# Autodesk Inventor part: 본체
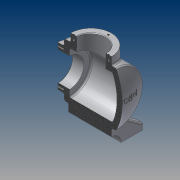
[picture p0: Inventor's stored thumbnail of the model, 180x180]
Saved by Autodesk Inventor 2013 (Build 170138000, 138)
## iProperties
Created: 2017-04
Part Number: 본체
Material: 알루미늄 6061
Document SubType Name: Modeling
Designer: Administrator
Density: 2.71 g/cm^3
Mass: 1670.76 g
Surface Area: 1066.85 cm^2
Volume: 616.515 cm^3
Author: Administrator
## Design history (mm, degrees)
sketch "스케치1"
  geometry: L1 (40, -60)-(-40, -60); L2 (-40, -60)-(-40, 60); L3 (-40, 60)-(40, 60); L4 (40, 60)-(40, -60); 3 further points
  constraints: 8 end point, 2 midpoint, 2 parallel, 1 horizontal, 1 horizontal alignment, 1 perpendicular, 1 vertical alignment
  dimensions: "d0" = 80 distance of L2.end L3.end; "d2" = 120 distance of L1.end L2.end
extrude "돌출1" new body sketch "스케치1" distance "d3" = 10; taper "d4" = 0 deg
sketch "스케치3"
  geometry: L1 (-60, 82)-(60, 82); L2 (-40, 0)-(-40, 10) reference; L3 (-40, 10)-(40, 10) reference; L4 (40, 10)-(40, 0) reference; L5 (40, 0)-(-40, 0) reference; L6 (-60, 82)-(-60, 120); L7 (-60, 120)-(-48, 120); L8 (-48, 120)-(-48, 132); L9 (-48, 132)-(48.336, 132); A1 r 113 centre (-53, 82) between (60, 82) and (48.336, 132); 2 further points
  constraints: 10 end point, 2 parallel, 2 perpendicular, 2 point on circle, 1 centre point, 1 horizontal, 1 midpoint, 1 point on line, 1 vertical alignment
  dimensions: "d5" = 82 distance between parallel lines of L5 L1; "d6" = 120 distance of L1.start L1.end; "d7" = 76 diameter of L7 L1; "d8" = 100 diameter of L9 L1; "d11" = 113 radius of A1; "d104" = 108 distance from line of L1.end L8
revolve "회전1" sketch "스케치3" stored, may be unused: angle "d12" = 90 deg
sketch "스케치4"
  geometry: L1 (-40, 0)-(-40, 10) reference; L2 (-40, 10)-(40, 10) reference; L3 (40, 10)-(40, 0) reference; L4 (40, 0)-(-40, 0) reference; L5 (-60, 44)-(-60, 120) reference; L6 (-60, 120)-(-48, 120) reference; L7 (-48, 120)-(-48, 132) reference; L8 (-48, 132)-(48.336, 132) reference; L9 (48.336, 32)-(-48, 32) reference; L10 (-48, 32)-(-48, 44) reference; L11 (-48, 44)-(-60, 44) reference; L12 (-60, 82)-(60, 82); L13 (41.916, 122)-(-38, 122); L14 (-38, 122)-(-38, 109); L15 (-38, 109)-(-60, 109); A1 r 113 centre (-53, 82) between (48.336, 32) and (48.336, 132) reference; A2 r 103 centre (-53, 82) between (50, 82) and (41.916, 122); 1 further point
  constraints: 8 end point, 3 point on circle, 2 point on line, 1 centre point, 1 midpoint, 1 other
  dimensions: "d14" = 10 radial gap between concentric circles of A1 A2; "d15" = 54 diameter of L15 L12; "d16" = 80 diameter of L13 L12
revolve "회전2" sketch "스케치4" stored, may be unused: angle "d17" = 90 deg
node "작업 평면1"
sketch "스케치5"
  geometry: L1 (48, 50)-(48, -50) reference; C1 r 38 at (-2, 0); 1 further point
  constraints: 1 centre point, 1 horizontal alignment
  dimensions: "d81" = 76 diameter of C1; "d82" = 50 distance from line of L1 C1.centre
extrude "돌출2" join sketch "스케치5" stored distance "d20" = 10; taper "d21" = 0 deg
sketch "스케치7" dims "d25" = 65
  geometry: C1 r 27 at (0, 0) reference; C2 r 38 at (0, 0) reference; 3 further points
  constraints: 2 vertical alignment, 1 coincident, 2 other
hole "구멍1" sketch "스케치7" at (0, 32.5) diameter "d26" = 3.242; stored, may be unused: countersink angle "d30" = 90 deg, drill point angle "d32" = 120 deg; dims "d27" = 8, "d28" = 4, "d29" = 2, "d31" = 10
sketch "스케치9"
  geometry: L1 (120, 0)-(120, 10) reference; L2 (0, 0)-(0, 10) reference; L3 (120, 10)-(120, 0) reference; L4 (120, 0)-(0, 0) reference; L5 (0, 0)-(0, 10) reference; L6 (0, 10)-(120, 10) reference; L7 (120, 10)-(81.584, 36.899); L8 (0, 10)-(38.416, 36.899); C1 r 27 at (60, 82) reference; A1 r 50 centre (60, 82) between (81.584, 36.899) and (38.416, 36.899) reference; 1 further point
  constraints: 4 end point, 2 point on circle
  dimensions: "d48" = 55 deg angle of L1 L7; "d49" = 55 deg angle of L2 L8
extrude "돌출4" join sketch "스케치9" distance "d50" = 80; taper "d51" = 0 deg
sketch "스케치10"
  geometry: L1 (120, 0)-(0, 0) reference; C1 r 18 at (60, 0); 2 further points
  constraints: 1 centre point, 1 coincident, 1 midpoint
  dimensions: "d52" = 36 diameter of C1
extrude "돌출5" cut sketch "스케치10" distance "d53" = 80; taper "d54" = 0 deg
sketch "스케치11"
  geometry: L1 (-40, 60)-(-40, 18) reference; C1 r 4 at (-20, 50); 2 further points
  constraints: 1 centre point
  dimensions: "d55" = 8 diameter of C1; "d56" = 20 distance from line of L1 C1.centre; "d103" = 10 vertical distance of C1.centre point (40, 60)
extrude "돌출6" cut sketch "스케치11" distance "d58" = 25; taper "d59" = 0 deg
node "작업 평면2"
sketch "스케치12"
  geometry: L1 (40, 16.971)-(-40, 16.971) reference; L2 (-40, 16.971)-(-40, 60) reference; L3 (-40, 60)-(40, 60) reference; L4 (40, 60)-(40, 16.971) reference; L5 (-40, -16.971)-(40, -16.971) reference; L6 (40, -16.971)-(40, -60) reference; L7 (40, -60)-(-40, -60) reference; L8 (-40, -60)-(-40, -16.971) reference; L9 (28, -50)-(28, -60); L10 (12, -50)-(12, -60); L11 (-12, -50)-(-12, -60); L12 (-28, -50)-(-28, -60); L13 (-28, 50)-(-28, 60); L14 (-12, 50)-(-12, 60); L15 (12, 50)-(12, 60); L16 (28, 50)-(28, 60); C1 r 4 at (-20, -50) reference; C2 r 4 at (20, -50) reference; C3 r 4 at (-20, 50) reference; C4 r 4 at (20, 50) reference; A1 r 8 centre (20, 50) between (12, 50) and (28, 50); A2 r 8 centre (-20, 50) between (-28, 50) and (-12, 50); A3 r 8 centre (20, -50) between (28, -50) and (12, -50); A4 r 8 centre (-20, -50) between (-12, -50) and (-28, -50); 1 further point
  constraints: 16 end point, 8 point on circle, 8 point on line, 8 tangent, 6 perpendicular, 4 centre point, 4 coincident, 2 parallel
  dimensions: "d61" = 16 diameter of A1; "d62" = 16 diameter of A2; "d64" = 16 diameter of A3; "d65" = 16 diameter of A4
extrude "돌출7" cut sketch "스케치12" distance "d66" = 25; taper "d67" = 0 deg
node "작업 평면3"
sketch "스케치13"
  geometry: 2 further points
  constraints: 1 horizontal alignment, 1 other
  dimensions: "d68" = 82 distance of point (-82, 0) point (0, 0)
feature "엠보싱1" sketch "스케치13" dims "d0" = 80, "d2" = 120, "d69" = 0.5, "d70" = 0
fillet "모깎기1" dims "d74" = 3
fillet "모깎기2" dims "d75" = 3
fillet "모깎기3" dims "d76" = 3
chamfer "모따기1" distance "d71" = 1; stored, may be unused: second distance "d72" = 2, angle "d73" = 45 deg
sketch "스케치15"
  geometry: C1 r 38 at (0, 0) reference; C2 r 27 at (0, 0); 1 further point
  constraints: 1 centre point, 1 coincident
  dimensions: "d85" = 54 diameter of C2
extrude "돌출8" cut sketch "스케치15" distance "d86" = 50; taper "d87" = 0 deg
sketch "스케치16" dims "d88" = 65
  geometry: C1 r 27 at (0, 0) reference; 3 further points
  constraints: 2 vertical alignment, 1 coincident, 2 other
hole "구멍3" sketch "스케치16" at (0, 32.5) diameter "d89" = 3.242; stored, may be unused: countersink angle "d93" = 90 deg, drill point angle "d95" = 120 deg; dims "d90" = 8, "d91" = 4, "d92" = 2, "d94" = 10
chamfer "모따기2" distance "d99" = 1; stored, may be unused: second distance "d100" = 2, angle "d101" = 45 deg
node "솔리드1"
pattern_circular "원형 패턴1" dims angle "d34" = 360 deg
mirror "대칭1"
mirror "대칭2"
pattern_circular "원형 패턴3" dims angle "d97" = 360 deg
node "절단 모서리 투영1"
node "절단 모서리 투영2"
node "절단 모서리 투영3"
node "절단 모서리 투영4"
other parameters: "d18" = 147, "d60" = 6, "d77" = 0.5, "d78" = 2, "d79" = 0
